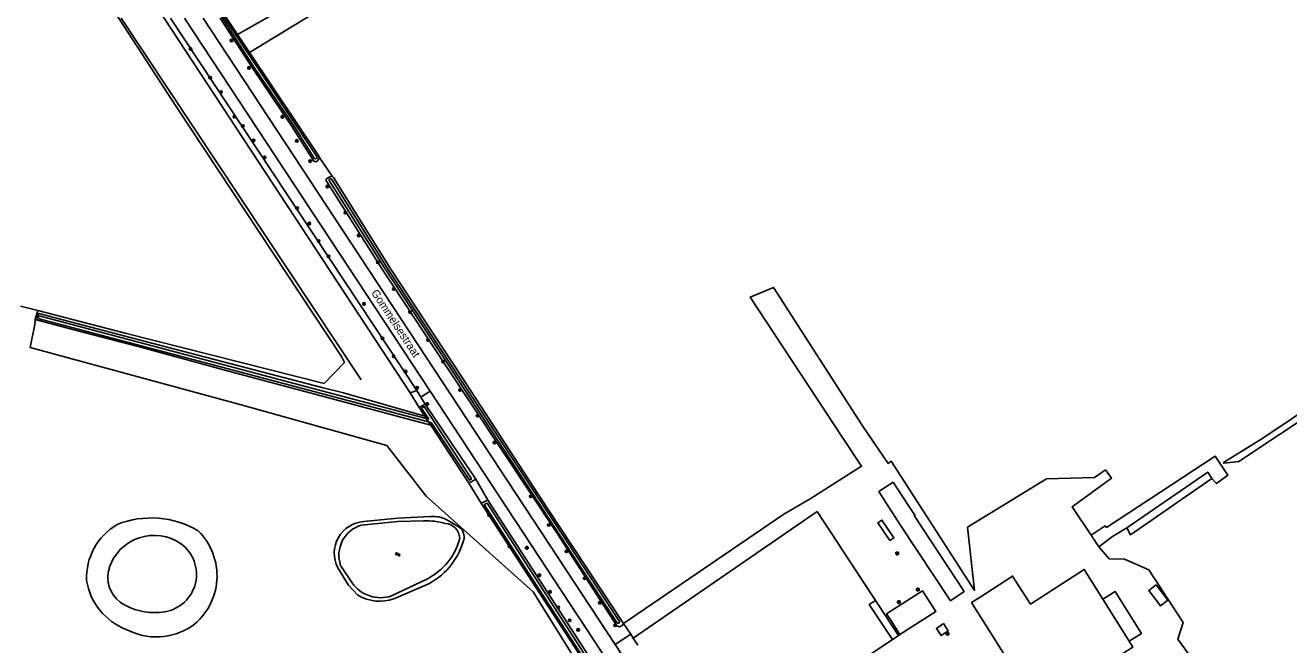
# Model space of a CAD drawing. Extents: x 137000 to 140001, y 403500 to 406000.
# Drawn here: x 138520.7 to 138915.5, y 405304.2 to 405497.8 of the extents above; entities that cross this region are included whole.
import ezdxf

# ---------------------------------------------------------------- set-up
doc = ezdxf.new("R2010")
doc.units = 0
for name, color, linetype in [('gg-afsc-draadraster', 7, 'Continuous'), ('gg-afsc-erfafscheiding', 7, 'Continuous'), ('gg-afsc-hekwerk', 7, 'Continuous'), ('gg-afsc-lijn draadraster', 7, 'Continuous'), ('gg-anno-openbare ruimte label', 7, 'Continuous'), ('gg-bbg-bijgebouw', 7, 'Continuous'), ('gg-bbg-luifel en loopbrug', 7, 'Continuous'), ('gg-bbg-open loods', 7, 'Continuous'), ('gg-bbg-overig bouwwerk', 7, 'Continuous'), ('gg-knt-bronhoudergrens', 7, 'Continuous'), ('gg-knt-onverhard', 7, 'Continuous'), ('gg-knt-verharding', 7, 'Continuous'), ('gg-kntw-bovenkant insteek waterloop', 7, 'Continuous'), ('gg-kntw-midden sloot', 7, 'Continuous'), ('gg-kntw-waterlijn', 7, 'Continuous'), ('gt-grn-groengrens', 7, 'Continuous'), ('gt-grn-groengrens NZ', 7, 'Continuous'), ('gt-grn-vlakafsluiter', 7, 'Continuous'), ('gt-grn-weggrens', 7, 'Continuous'), ('gt-symb-boom', 7, 'Continuous'), ('gt-symb-lichtmast', 7, 'Continuous'), ('gt-symb-watersymbool', 7, 'Continuous')]:
    doc.layers.add(name, color=color, linetype=linetype)

# ---------------------------------------------------------------- blocks, each defined once
blk = doc.blocks.new('gt0-LMAST')
at = {"layer": 'gt-symb-lichtmast'}
for p, q in [((-0.18, 0.17), (-0.45, 0.44)), ((-0.01, 0.25), (-0.01, 0.62)), ((0.17, 0.17), (0.44, 0.44)), ((-0.26, 0), (-0.63, 0)), ((-0.18, -0.18), (-0.45, -0.45)), ((-0.01, -0.25), (-0.01, -0.63)), ((0.44, -0.45), (0.17, -0.18)), ((0.24, 0), (0.62, 0))]:
    blk.add_line(p, q, dxfattribs=at)
blk.add_circle((-0.01, 0), 0.25, dxfattribs=at)
blk = doc.blocks.new('gt0-BOOM')
at = {"layer": 'gt-symb-boom'}
for radius in [0.4, 0.2]:
    blk.add_circle((0, 0), radius, dxfattribs=at)
blk = doc.blocks.new('gt0-WA')
at = {"layer": 'gt-symb-watersymbool'}
for centre, start, end in [((-0.32, 0.02), 28.0725, 151.9275), ((0.43, 0.42), 208.0725, 331.9275), ((-0.32, -0.43), 28.0725, 151.9275), ((0.43, -0.03), 208.0725, 331.9275)]:
    blk.add_arc(centre, 0.425, start, end, dxfattribs=at)

msp = doc.modelspace()

# ---------------------------------------------------------------- linework, layer by layer
at = {"layer": 'gg-afsc-draadraster'}
for q in [(138519.23, 405410.03), (138523.88, 405405.81)]:
    msp.add_line((138524.64, 405408.62), q, dxfattribs=at)
for points in [[(138285.47, 405546.77), (138385.85, 405542.03), (138429.7, 405539.4), (138436.46, 405539.56), (138519.15, 405547.11), (138520.63, 405545.63), (138532.33, 405527.32), (138568.1, 405472.11), (138619.55, 405394.28), (138620.49, 405392.37), (138614.17, 405385.79)], [(138523.88, 405405.81), (138523.73, 405404.25), (138522.27, 405397.01), (138588.23, 405379.11), (138633.76, 405366.43), (138646.03, 405350.6), (138679.46, 405320.68), (138708.58, 405273.78)], [(138614.17, 405385.79), (138551.92, 405401.53), (138524.64, 405408.62)]]:
    msp.add_lwpolyline(points, dxfattribs=at)
at = {"layer": 'gg-afsc-erfafscheiding'}
for p, q in [((138659.36, 405354.64), (138663.25, 405348.39)), ((138707.72, 405310.79), (138709.94, 405307.43)), ((138709.94, 405307.43), (138710.73, 405306.25))]:
    msp.add_line(p, q, dxfattribs=at)
at = {"layer": 'gg-afsc-hekwerk'}
for p, q in [((138793.65, 405307.03), (138768.16, 405345.78)), ((138793.65, 405307.03), (138736.89, 405269.22)), ((138794.01, 405307.27), (138793.65, 405307.03))]:
    msp.add_line(p, q, dxfattribs=at)
at = {"layer": 'gg-afsc-lijn draadraster'}
for q in [(138519.23, 405410.03), (138523.88, 405405.81)]:
    msp.add_line((138524.64, 405408.62), q, dxfattribs=at)
for points in [[(138285.47, 405546.77), (138385.85, 405542.03), (138429.7, 405539.4), (138436.46, 405539.56), (138519.15, 405547.11), (138520.63, 405545.63), (138532.33, 405527.32), (138568.1, 405472.11), (138619.55, 405394.28), (138620.49, 405392.37), (138614.17, 405385.79)], [(138523.88, 405405.81), (138523.73, 405404.25), (138522.27, 405397.01), (138588.23, 405379.11), (138633.76, 405366.43), (138646.03, 405350.6), (138679.46, 405320.68), (138708.58, 405273.78)]]:
    msp.add_lwpolyline(points, dxfattribs=at)
at = {"layer": 'gg-bbg-bijgebouw'}
msp.add_line((138865.68, 405305.29), (138857.45, 405318.42), dxfattribs=at)
for points in [[(138791.97, 405354.95), (138796.87, 405347.44), (138798.71, 405344.61), (138798.53, 405344.5), (138814.16, 405320.8), (138809.8, 405317.93), (138794.17, 405341.63), (138787.49, 405352.09), (138791.97, 405354.95)], [(138857.45, 405318.42), (138851.63, 405327.72), (138834.89, 405316.87)], [(138834.89, 405316.87), (138829.23, 405325.6), (138818.83, 405318.86), (138816.45, 405317.32), (138837.76, 405283.47), (138850.45, 405291.59), (138849.76, 405292.69), (138866.86, 405303.4), (138865.68, 405305.29)]]:
    msp.add_lwpolyline(points, dxfattribs=at)
at = {"layer": 'gg-bbg-luifel en loopbrug'}
for points in [[(138790.91, 405336.71), (138792.15, 405337.55), (138788.4, 405343.11), (138787.16, 405342.27), (138790.91, 405336.71)], [(138865.68, 405305.29), (138869.49, 405307.68), (138861.27, 405320.81), (138857.45, 405318.42)]]:
    msp.add_lwpolyline(points, dxfattribs=at)
at = {"layer": 'gg-bbg-open loods'}
msp.add_lwpolyline([(138791.16, 405311.79), (138789.87, 405313.8), (138801.06, 405321.01), (138805.23, 405314.54), (138794.04, 405307.33), (138791.16, 405311.79)], dxfattribs=at)
at = {"layer": 'gg-bbg-overig bouwwerk'}
for points in [[(138877.74, 405318.07), (138874.1, 405322.86), (138871.8, 405321.11), (138875.43, 405316.32), (138877.74, 405318.07)], [(138807.71, 405310.75), (138805.44, 405309.28), (138806.91, 405307.01), (138809.17, 405308.48), (138807.71, 405310.75)]]:
    msp.add_lwpolyline(points, dxfattribs=at)
at = {"layer": 'gg-knt-bronhoudergrens'}
for p, q in [((138616.6, 405450.65), (138612.53, 405456.52)), ((138790.39, 405360.82), (138787.48, 405365.09)), ((138712.17, 405304.07), (138710.73, 405306.25))]:
    msp.add_line(p, q, dxfattribs=at)
for points in [[(138999.99, 405430.79), (138907.08, 405368.55), (138895.12, 405361.09), (138895.24, 405360.89), (138899.95, 405361.46), (139001.01, 405428.49), (138999.99, 405430.79)], [(138707.72, 405310.79), (138757.8, 405344.92), (138765.97, 405349.76), (138782.08, 405359.95), (138776.09, 405368.89), (138747.29, 405412.79), (138754.56, 405415.83), (138782.14, 405372.84), (138787.48, 405365.09)], [(138853.8, 405338.42), (138858.16, 405341.35), (138858.64, 405340.8), (138892.53, 405363.1), (138896.5, 405357.15), (138892.93, 405354.53), (138891.48, 405356.09)], [(138853.8, 405338.42), (138847.88, 405347.26), (138860.16, 405356.25), (138858.23, 405358.8), (138854.83, 405356.46), (138839.83, 405356), (138815.21, 405340.93), (138817.35, 405321.16), (138791.31, 405361.51), (138790.39, 405360.82)], [(138891.48, 405356.09), (138890.25, 405358.05), (138864.92, 405340.66)], [(138891.48, 405356.09), (138866.12, 405338.51), (138864.92, 405340.66)], [(138736.89, 405269.22), (138791.75, 405305.76), (138784.46, 405316.69), (138786.44, 405318), (138768.16, 405345.78)], [(138864.92, 405340.66), (138860.46, 405338.02), (138856.23, 405334.79)], [(138856.23, 405334.79), (138859.41, 405331.04), (138864.24, 405330.89), (138871.87, 405327.56), (138882.59, 405311.12), (138880.93, 405305.94), (138884.45, 405300.97), (138877.69, 405296.48), (138892.82, 405273.73), (138898.15, 405277.02), (138902.27, 405270.35), (138896.95, 405267.06), (138896.34, 405268.05), (138886.66, 405261.7), (138885.68, 405262.86), (138881.67, 405259.84)]]:
    msp.add_lwpolyline(points, dxfattribs=at)
at = {"layer": 'gg-knt-onverhard'}
msp.add_line((138710.73, 405306.25), (138768.16, 405345.78), dxfattribs=at)
at = {"layer": 'gg-knt-verharding'}
for p, q in [((138570.51, 405500), (138647.23, 405383.38)), ((138576.29, 405500), (138705.1, 405304.24)), ((138647.23, 405383.38), (138703, 405298.59)), ((138750.03, 405235.96), (138705.1, 405304.24))]:
    msp.add_line(p, q, dxfattribs=at)
at = {"layer": 'gg-kntw-bovenkant insteek waterloop'}
for p, q in [((138587.09, 405494.89), (138565.57, 405527.2)), ((138590.85, 405489.25), (138587.09, 405494.89)), ((138643.8, 405378.34), (138645.65, 405379.33)), ((138643.8, 405378.34), (138644.55, 405377.19)), ((138661.49, 405355.88), (138645.65, 405379.33)), ((138644.55, 405377.19), (138645.57, 405375.65)), ((138659.36, 405354.64), (138647.43, 405372.82)), ((138659.36, 405354.64), (138661.49, 405355.88)), ((138665.3, 405349.36), (138663.25, 405348.39)), ((138663.25, 405348.39), (138696.17, 405297.55)), ((138665.3, 405349.36), (138698.22, 405298.51)), ((138656, 405341.15), (138652.48, 405343.24)), ((138635.9, 405318.55), (138647.01, 405323.31))]:
    msp.add_line(p, q, dxfattribs=at)
for points in [[(138581.67, 405500), (138591.86, 405484.24), (138603.98, 405466.37), (138610.91, 405455.35), (138611.5, 405455.08), (138612.09, 405455.37), (138612.35, 405455.87), (138612.53, 405456.52)], [(138612.53, 405456.52), (138612.32, 405457.03), (138590.85, 405489.25)], [(138707.72, 405310.79), (138707.29, 405310.17), (138706.4, 405309.8), (138705.57, 405310.03), (138686.89, 405339.12), (138652.02, 405391.59), (138632.31, 405421.5), (138614.67, 405449.4), (138614.84, 405449.77), (138615.71, 405450.35), (138616.6, 405450.65)], [(138707.72, 405310.79), (138683.95, 405346.71), (138657.09, 405388), (138635.02, 405421.58), (138617.1, 405450.16), (138616.6, 405450.65)], [(138523.88, 405405.81), (138524.99, 405407.73), (138532.52, 405405.69), (138562.7, 405397.83), (138613.84, 405384.49)], [(138523.88, 405405.81), (138536.32, 405402.46), (138556.07, 405397.38), (138584.62, 405389.52), (138612.81, 405382.02), (138647.43, 405372.82)], [(138613.84, 405384.49), (138620.17, 405382.85), (138645.57, 405375.65)], [(138626.5, 405342.68), (138637.13, 405343.75), (138647.4, 405344.21)], [(138624.69, 405319.67), (138621.76, 405322.75), (138618.41, 405328.23)]]:
    msp.add_lwpolyline(points, dxfattribs=at)
for centre, radius, start, end in [((138560.13, 405315.07), 28.71, 59.3972, 111.7078), ((138627.25, 405332.77), 9.94, 94.3322, 207.1743), ((138648.25, 405334.87), 9.38, 63.1489, 95.1779), ((138559.26, 405325.03), 19.36, 120.2615, 182.3104), ((138560.97, 405325.7), 19.7, 306.8542, 45.6255), ((138654.16, 405337.91), 3.72, 352.1959, 60.3201), ((138636.35, 405342.72), 22.15, 298.7665, 346.1003), ((138559.21, 405327.2), 19.51, 188.7131, 249.2156), ((138631.44, 405330.54), 12.79, 238.1577, 290.406), ((138561.71, 405326.6), 20, 241.8666, 303.6179)]:
    msp.add_arc(centre, radius, start, end, dxfattribs=at)
at = {"layer": 'gg-kntw-midden sloot'}
msp.add_line((138550.75, 405500), (138625.68, 405386.95), dxfattribs=at)
at = {"layer": 'gg-kntw-waterlijn'}
for p, q in [((138524.65, 405406.12), (138525.11, 405406.93)), ((138524.65, 405406.12), (138646.78, 405373.79)), ((138525.11, 405406.93), (138646.05, 405374.92)), ((138644.58, 405378.11), (138646.83, 405374.71)), ((138646.05, 405374.92), (138646.83, 405374.71)), ((138646.78, 405373.79), (138647.58, 405373.58)), ((138622.91, 405323.54), (138619.26, 405328.96)), ((138646.27, 405324.68), (138635.22, 405319.43))]:
    msp.add_line(p, q, dxfattribs=at)
for points in [[(138565.32, 405525.86), (138582.13, 405500.3), (138592.32, 405484.54), (138604.44, 405466.67), (138611.02, 405456.21)], [(138611.83, 405456.77), (138590.4, 405488.95), (138586.64, 405494.59), (138565.69, 405526.04)], [(138705.61, 405311.13), (138652.7, 405392.04), (138632.99, 405421.94), (138615.74, 405449.22)], [(138706.44, 405311.46), (138656.42, 405387.56), (138634.35, 405421.14), (138616.55, 405449.53)], [(138647.58, 405373.58), (138659.52, 405355.56), (138660.17, 405355.99), (138645.43, 405378.58), (138644.58, 405378.11)], [(138664.15, 405348.03), (138696.18, 405298.41), (138696.98, 405298.93), (138665.04, 405348.42), (138664.15, 405348.03)], [(138625.67, 405341.51), (138637.2, 405342.72), (138645.18, 405342.87)]]:
    msp.add_lwpolyline(points, dxfattribs=at)
for centre, radius, start, end in [((138611.42, 405456.5), 0.496, 215.5936, 33.2925), ((138616.15, 405449.37), 0.431, 21, 201.5905), ((138645.96, 405318.52), 24.36, 75.4297, 91.8353), ((138628.58, 405332.11), 9.84, 107.1933, 198.6547), ((138651.55, 405337.16), 4.97, 3.5248, 83.8595), ((138561.02, 405323.62), 14.73, 55.3988, 161.9439), ((138562.37, 405326.16), 11.88, 279.7429, 53.8195), ((138637.11, 405342.53), 20.06, 297.1738, 345.3755), ((138556.29, 405325.21), 9.73, 162.2149, 232.7032), ((138631.78, 405329.61), 10.75, 214.381, 288.643), ((138561.28, 405333.95), 19.75, 236.5468, 279.0485), ((138706.02, 405311.29), 0.447, 201.6808, 21.8029)]:
    msp.add_arc(centre, radius, start, end, dxfattribs=at)
at = {"layer": 'gt-grn-groengrens'}
for p, q in [((138566.17, 405500), (138643.11, 405383.67)), ((138640.98, 405382.9), (138643.8, 405378.34))]:
    msp.add_line(p, q, dxfattribs=at)
msp.add_lwpolyline([(138590.85, 405489.25), (138617.65, 405505.69), (138615.19, 405510.98), (138587.09, 405494.89)], dxfattribs=at)
at = {"layer": 'gt-grn-groengrens NZ'}
for p, q in [((138643.11, 405383.67), (138640.98, 405382.9)), ((138643.11, 405383.67), (138644.38, 405381.5)), ((138644.38, 405381.5), (138645.65, 405379.33)), ((138661.49, 405355.88), (138665.3, 405349.36))]:
    msp.add_line(p, q, dxfattribs=at)
msp.add_lwpolyline([(138640.98, 405382.9), (138564.2, 405500), (138530.63, 405550.76)], dxfattribs=at)
at = {"layer": 'gt-grn-vlakafsluiter'}
for p, q in [((138645.57, 405375.65), (138646.05, 405374.92)), ((138646.78, 405373.79), (138646.05, 405374.92)), ((138647.43, 405372.82), (138646.78, 405373.79)), ((138853.8, 405338.42), (138856.23, 405334.79))]:
    msp.add_line(p, q, dxfattribs=at)
at = {"layer": 'gt-grn-weggrens'}
for p, q in [((138647.23, 405383.38), (138644.38, 405381.5)), ((138705.1, 405304.24), (138709.94, 405307.43))]:
    msp.add_line(p, q, dxfattribs=at)

# ---------------------------------------------------------------- block references
at = {"layer": 'gt-symb-boom'}
for p in [(138585.21, 405493.04), (138572.4, 405490.39), (138590.66, 405484.48), (138578.5, 405481.39), (138581.91, 405476.91), (138586.07, 405469.2), (138601.08, 405469.17), (138588.71, 405466.28), (138592.11, 405461.79), (138605.6, 405461.63), (138595.49, 405456.43), (138609.77, 405455.33), (138615.15, 405447.37), (138605.71, 405440.62), (138620.83, 405439.22), (138609.51, 405435.81), (138612.44, 405430.33), (138624.93, 405432.08), (138615.5, 405425.55), (138630.92, 405423.68), (138635.87, 405415.36), (138626.6, 405410.72), (138640.95, 405408.13), (138632.35, 405399.9), (138646.58, 405399.4), (138635.85, 405394.32), (138639.57, 405389.54), (138651.27, 405392.64), (138643.21, 405384.48), (138656.63, 405383.78), (138646.37, 405379.43), (138662.08, 405375.76), (138667.37, 405367.39), (138678.74, 405350.54), (138665.69, 405344.69), (138684.34, 405341.57), (138672.02, 405334.93), (138689.83, 405333.36), (138681.4, 405325.88), (138695.51, 405324.91), (138684.71, 405320.67), (138687.31, 405315.82), (138700.3, 405317.28), (138690.83, 405311.8), (138693.51, 405308.82), (138705.07, 405310.23)]:
    msp.add_blockref('gt0-BOOM', p, dxfattribs=at)
at = {"layer": 'gt-symb-lichtmast'}
for p in [(138677.47, 405334.47), (138793.22, 405332.73), (138799.65, 405321.38), (138793.71, 405317.5), (138808.91, 405307.6)]:
    msp.add_blockref('gt0-LMAST', p, dxfattribs=at)
at = {"layer": 'gt-symb-watersymbool'}
msp.add_blockref('gt0-WA', (138637.11, 405332.4), dxfattribs=at)

# ---------------------------------------------------------------- texts
at = {"layer": 'gg-anno-openbare ruimte label'}
msp.add_text('Gommelsestraat', height=2.5, rotation=303.4, dxfattribs=at).set_placement((138628.73, 405414.17))

doc.saveas('drawing.dxf')
